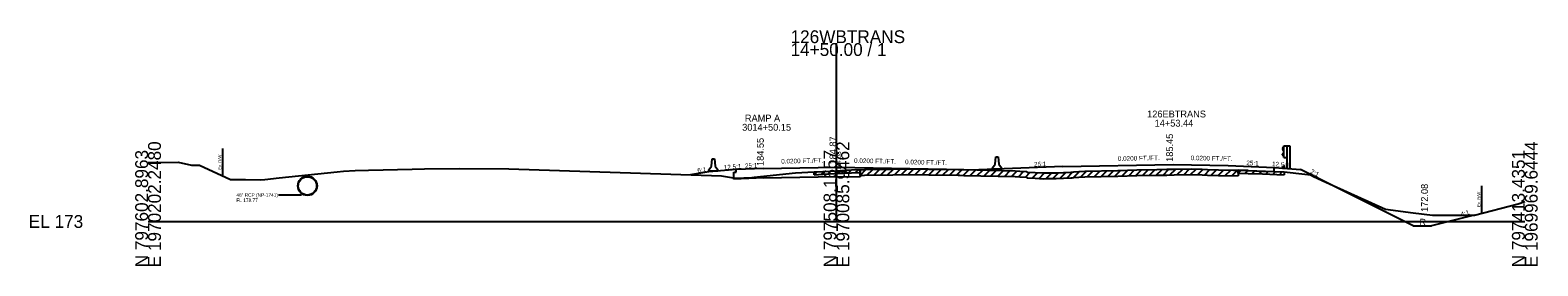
# Model space of a CAD drawing. Extents: x -6494 to 1970605, y -10 to 798140.
# Drawn here: x -25.7 to 302.8, y 6990.3 to 7041.8 of the extents above; entities that cross this region are included whole.
import ezdxf

# ---------------------------------------------------------------- set-up
doc = ezdxf.new("R2010")
doc.units = 0
for name, color, linetype in [('Default', 7, 'Continuous'), ('RD_GPK_XS_Cell', 7, 'Continuous'), ('RD_XS_Base', 7, 'Continuous'), ('RD_XS_CurbTop', 7, 'Continuous'), ('RD_XS_EarthShd', 7, 'Continuous'), ('RD_XS_ExGround', 7, 'Continuous'), ('RD_XS_ExPaveRet', 7, 'Continuous'), ('RD_XS_ExRW', 7, 'Continuous'), ('RD_XS_GR', 7, 'Continuous'), ('RD_XS_Misc_Line', 7, 'Continuous'), ('RD_XS_Pave', 7, 'Continuous'), ('RD_XS_PaveOvlay', 7, 'Continuous'), ('RD_XS_PaveShd', 7, 'Continuous'), ('RD_XS_Pipe', 7, 'Continuous'), ('RD_XS_TieSlope', 7, 'Continuous'), ('RD_XS_TX_Elev_EX', 7, 'Continuous'), ('RD_XS_TX_Elev_PR', 7, 'Continuous'), ('RD_XS_TX_Misc', 7, 'Continuous'), ('RD_XS_TX_MkPT', 7, 'Continuous'), ('RD_XS_TX_Profile', 7, 'Continuous'), ('RD_XS_TX_ShdSlope', 7, 'Continuous'), ('RD_XS_TX_Slope', 7, 'Continuous'), ('RD_XS_TX_Station', 7, 'Continuous')]:
    doc.layers.add(name, color=color, linetype=linetype)

msp = doc.modelspace()

# ---------------------------------------------------------------- linework, layer by layer
at = {"layer": 'Default'}
for p, q in [((122.16, 7011.24), (122.74, 7012.07)), ((122.16, 7010.99), (122.16, 7011.24)), ((124.16, 7010.99), (122.16, 7010.99)), ((122.74, 7012.07), (122.91, 7013.66)), ((122.91, 7013.66), (123.41, 7013.66)), ((123.41, 7013.66), (123.58, 7012.07)), ((123.58, 7012.07), (124.16, 7011.24)), ((124.16, 7011.24), (124.16, 7010.99)), ((184, 7011.67), (184.58, 7012.5)), ((184, 7011.42), (184, 7011.67)), ((186, 7011.42), (184, 7011.42)), ((184.58, 7012.5), (184.75, 7014.08)), ((184.75, 7014.08), (185.25, 7014.08)), ((185.25, 7014.08), (185.42, 7012.5)), ((185.42, 7012.5), (186, 7011.67)), ((186, 7011.67), (186, 7011.42))]:
    msp.add_line(p, q, dxfattribs=at)
at = {"layer": 'RD_GPK_XS_Cell'}
for p, q in [((150, 7000), (150, 7038.91)), ((0, 7000), (150, 7000)), ((150, 7000), (300, 7000))]:
    msp.add_line(p, q, dxfattribs=at)
at = {"layer": 'RD_XS_Base'}
for p, q in [((128.16, 7010.75), (128.16, 7011.31)), ((245.35, 7010.89), (245.35, 7011.81)), ((127.66, 7010.73), (128.16, 7010.75)), ((127.66, 7009.25), (127.66, 7010.73)), ((134.17, 7009.51), (127.66, 7009.25)), ((134.17, 7009.51), (138, 7009.59)), ((138, 7009.59), (150, 7009.83)), ((150, 7009.83), (155.15, 7009.73))]:
    msp.add_line(p, q, dxfattribs=at)
at = {"layer": 'RD_XS_CurbTop'}
for p, q in [((247.23, 7011.66), (247.47, 7012.12)), ((247.23, 7011.66), (247.69, 7011.62)), ((247.69, 7011.62), (247.63, 7012.06))]:
    msp.add_line(p, q, dxfattribs=at)
msp.add_ellipse((247.54, 7012.04), major_axis=(0, -0.131), ratio=0.686, start_param=1.762783, end_param=4.036677, dxfattribs=at)
at = {"layer": 'RD_XS_EarthShd'}
for p, q in [((128.16, 7011.31), (122.16, 7010.83)), ((245.35, 7011.81), (247.35, 7011.65))]:
    msp.add_line(p, q, dxfattribs=at)
at = {"layer": 'RD_XS_ExGround'}
msp.add_lwpolyline([(0, 7012.9), (6.53, 7012.97), (9.43, 7012.28), (11.23, 7012.29), (17.94, 7009.16), (20.84, 7009.14), (21.23, 7009.14), (24.41, 7009.12), (25.44, 7009.17), (28.59, 7009.49), (41.22, 7010.81), (42.59, 7010.95), (45.11, 7011.15), (48.04, 7011.21), (57.57, 7011.43), (60.26, 7011.47), (67.86, 7011.57), (78.64, 7011.45), (124.99, 7009.94), (128.04, 7009.42), (131.56, 7009.61), (132.09, 7009.66), (141.09, 7010.58), (145.14, 7010.81), (147.07, 7010.92), (150, 7011.08), (153.28, 7011.27), (156.11, 7011.32), (162.29, 7011.44), (165.17, 7011.5), (170.13, 7011.43), (176.5, 7011.34), (176.87, 7011.33), (177.74, 7011.31), (188.97, 7011.07), (189.98, 7011), (191.31, 7010.91), (191.56, 7010.79), (193.34, 7010.69), (195.2, 7010.58), (196.12, 7010.61), (197.9, 7010.63), (201.05, 7010.74), (201.38, 7010.76), (201.71, 7010.86), (202.79, 7010.91), (204.11, 7010.97), (211.34, 7011.15), (215.43, 7011.25), (219.78, 7011.34), (221.97, 7011.38), (223.62, 7011.41), (227.37, 7011.47), (229.69, 7011.4), (230.82, 7011.36), (233.25, 7011.3), (239.73, 7011.12), (242.84, 7010.99), (247.56, 7010.8), (252.08, 7010.31), (253.31, 7010.18), (253.84, 7009.89), (255.81, 7008.94), (258.22, 7007.87), (269.61, 7002.67), (275.64, 7001.89), (279.85, 7001.41), (281.07, 7001.41), (289.01, 7001.41), (298.56, 7003.87), (300, 7004.35)], dxfattribs=at)
at = {"layer": 'RD_XS_ExPaveRet'}
for p, q in [((155.15, 7010.05), (155.15, 7011.3)), ((155.15, 7011.3), (155.15, 7010.68)), ((237.56, 7011.18), (237.56, 7009.93)), ((237.56, 7010.55), (237.56, 7011.18)), ((145.14, 7010.18), (145.14, 7010.81)), ((145.14, 7010.18), (147.07, 7010.29)), ((147.07, 7010.29), (150, 7010.46)), ((150, 7010.46), (153.28, 7010.64)), ((153.28, 7010.64), (155.15, 7010.68)), ((155.15, 7010.05), (156.11, 7010.07)), ((156.11, 7010.07), (162.29, 7010.19)), ((162.29, 7010.19), (165.17, 7010.25)), ((165.17, 7010.25), (170.13, 7010.18)), ((170.13, 7010.18), (176.5, 7010.09)), ((176.5, 7010.09), (176.87, 7010.08)), ((176.87, 7010.08), (177.74, 7010.06)), ((177.74, 7010.06), (188.97, 7009.82)), ((188.97, 7009.82), (189.98, 7009.75)), ((189.98, 7009.75), (191.31, 7009.66)), ((191.31, 7009.66), (191.56, 7009.54)), ((191.56, 7009.54), (193.34, 7009.44)), ((193.34, 7009.44), (195.2, 7009.33)), ((195.2, 7009.33), (196.12, 7009.36)), ((196.12, 7009.36), (197.9, 7009.38)), ((197.9, 7009.38), (201.05, 7009.49)), ((201.05, 7009.49), (201.38, 7009.51)), ((201.38, 7009.51), (201.71, 7009.61)), ((201.71, 7009.61), (202.79, 7009.66)), ((202.79, 7009.66), (204.11, 7009.72)), ((204.11, 7009.72), (211.34, 7009.9)), ((211.34, 7009.9), (215.43, 7010)), ((215.43, 7010), (219.78, 7010.09)), ((219.78, 7010.09), (221.97, 7010.13)), ((221.97, 7010.13), (223.62, 7010.16)), ((223.62, 7010.16), (227.37, 7010.22)), ((227.37, 7010.22), (229.69, 7010.15)), ((229.69, 7010.15), (230.82, 7010.11)), ((230.82, 7010.11), (233.25, 7010.05)), ((233.25, 7010.05), (237.56, 7009.93)), ((237.56, 7010.55), (239.73, 7010.49)), ((239.73, 7010.49), (242.84, 7010.36)), ((242.84, 7010.36), (247.56, 7010.17)), ((247.56, 7010.8), (247.56, 7010.17))]:
    msp.add_line(p, q, dxfattribs=at)
at = {"layer": 'RD_XS_ExRW'}
for p, q in [((16.23, 7015.9), (16.23, 7009.9)), ((290.56, 7007.81), (290.56, 7001.81))]:
    msp.add_line(p, q, dxfattribs=at)
at = {"layer": 'RD_XS_GR'}
for p, q in [((247.5, 7016.36), (247.23, 7015.92)), ((247.23, 7015.92), (247.23, 7015.81)), ((247.23, 7015.81), (247.5, 7015.37)), ((247.23, 7014.67), (247.5, 7015.11)), ((247.23, 7014.56), (247.23, 7014.67)), ((247.5, 7014.12), (247.23, 7014.56)), ((247.5, 7016.53), (248.16, 7016.53)), ((247.5, 7013.96), (247.5, 7016.53)), ((248.16, 7016.53), (248.83, 7016.53)), ((248.16, 7016.53), (248.16, 7011.58)), ((248.83, 7016.53), (248.83, 7011.47)), ((247.5, 7013.96), (248.16, 7013.96))]:
    msp.add_line(p, q, dxfattribs=at)
at = {"layer": 'RD_XS_Misc_Line'}
for p, q in [((146.64, 7010.27), (147.31, 7010.93)), ((148.15, 7010.35), (148.81, 7011.01)), ((149.65, 7010.44), (150.31, 7011.1)), ((151.15, 7010.52), (151.81, 7011.18)), ((152.65, 7010.61), (153.31, 7011.27)), ((154.15, 7010.66), (154.79, 7011.29)), ((155.15, 7010.05), (156.42, 7011.32)), ((156.65, 7010.08), (157.92, 7011.35)), ((158.15, 7010.11), (159.43, 7011.38)), ((159.65, 7010.14), (160.93, 7011.41)), ((161.15, 7010.16), (162.43, 7011.44)), ((162.65, 7010.19), (163.93, 7011.47)), ((164.15, 7010.23), (165.42, 7011.5)), ((165.65, 7010.24), (166.89, 7011.48)), ((167.15, 7010.22), (168.39, 7011.46)), ((168.66, 7010.2), (169.89, 7011.44)), ((170.16, 7010.18), (171.39, 7011.42)), ((171.66, 7010.16), (172.89, 7011.39)), ((173.16, 7010.14), (174.39, 7011.37)), ((174.66, 7010.12), (175.89, 7011.35)), ((176.16, 7010.09), (177.39, 7011.32)), ((177.66, 7010.07), (178.88, 7011.29)), ((179.16, 7010.03), (180.38, 7011.26)), ((180.66, 7010), (181.89, 7011.22)), ((182.16, 7009.97), (183.39, 7011.19)), ((183.66, 7009.93), (184.89, 7011.16)), ((185.16, 7009.9), (186.39, 7011.12)), ((186.66, 7009.87), (187.89, 7011.09)), ((188.17, 7009.83), (189.37, 7011.04)), ((189.67, 7009.77), (190.84, 7010.94)), ((201.67, 7009.6), (202.99, 7010.92)), ((203.17, 7009.68), (204.48, 7010.98)), ((204.67, 7009.73), (205.96, 7011.02)), ((206.17, 7009.77), (207.46, 7011.05)), ((207.68, 7009.81), (208.96, 7011.09)), ((209.18, 7009.85), (210.46, 7011.13)), ((210.68, 7009.89), (211.96, 7011.17)), ((212.18, 7009.92), (213.46, 7011.2)), ((213.68, 7009.96), (214.96, 7011.24)), ((215.18, 7009.99), (216.46, 7011.27)), ((216.68, 7010.02), (217.96, 7011.3)), ((218.18, 7010.05), (219.46, 7011.33)), ((219.68, 7010.08), (220.96, 7011.36)), ((221.18, 7010.11), (222.46, 7011.39)), ((222.68, 7010.14), (223.96, 7011.42)), ((224.18, 7010.17), (225.45, 7011.44)), ((225.68, 7010.19), (226.95, 7011.46)), ((227.18, 7010.22), (228.41, 7011.44)), ((228.69, 7010.18), (229.9, 7011.39)), ((230.19, 7010.13), (231.4, 7011.34)), ((231.69, 7010.09), (232.91, 7011.31)), ((233.19, 7010.05), (234.41, 7011.26)), ((234.69, 7010.01), (235.91, 7011.22)), ((236.19, 7009.97), (237.41, 7011.18)), ((237.56, 7010.55), (238.16, 7011.16)), ((239.06, 7010.51), (239.67, 7011.12)), ((240.56, 7010.46), (241.16, 7011.06)), ((242.06, 7010.4), (242.66, 7011)), ((243.56, 7010.34), (244.16, 7010.94)), ((145.14, 7010.18), (145.81, 7010.85)), ((191.17, 7009.67), (192.25, 7010.75)), ((192.67, 7009.48), (193.85, 7010.66)), ((194.17, 7009.39), (195.36, 7010.59)), ((195.67, 7009.35), (196.94, 7010.62)), ((197.17, 7009.37), (198.45, 7010.65)), ((198.67, 7009.41), (199.97, 7010.7)), ((200.17, 7009.46), (201.51, 7010.8)), ((245.06, 7010.27), (245.66, 7010.87)), ((246.56, 7010.21), (247.16, 7010.81))]:
    msp.add_line(p, q, dxfattribs=at)
at = {"layer": 'RD_XS_Pave'}
for p, q in [((134.17, 7011.55), (138, 7011.63)), ((138, 7011.63), (150, 7011.87)), ((150, 7011.87), (174, 7011.39)), ((199.35, 7011.97), (223.35, 7012.45)), ((223.35, 7012.45), (235.35, 7012.21))]:
    msp.add_line(p, q, dxfattribs=at)
at = {"layer": 'RD_XS_PaveOvlay'}
for p, q in [((155.15, 7011.3), (156.11, 7011.32)), ((155.15, 7011.3), (155.15, 7009.73)), ((156.11, 7011.32), (162.29, 7011.44)), ((162.29, 7011.44), (165.17, 7011.5)), ((165.17, 7011.5), (170.13, 7011.43)), ((170.13, 7011.43), (176.5, 7011.34)), ((176.5, 7011.34), (176.87, 7011.33)), ((176.87, 7011.33), (177.74, 7011.31)), ((177.74, 7011.31), (188.92, 7011.07)), ((188.97, 7011.07), (189.98, 7011)), ((189.98, 7011), (191.31, 7010.91)), ((191.31, 7010.91), (191.56, 7010.79)), ((201.71, 7010.86), (202.79, 7010.91)), ((202.79, 7010.91), (204.11, 7010.97)), ((204.11, 7010.97), (211.34, 7011.15)), ((211.34, 7011.15), (215.43, 7011.25)), ((215.43, 7011.25), (219.78, 7011.34)), ((219.78, 7011.34), (221.97, 7011.38)), ((221.97, 7011.38), (223.62, 7011.41)), ((223.62, 7011.41), (227.37, 7011.47)), ((227.37, 7011.47), (229.69, 7011.4)), ((229.69, 7011.4), (230.82, 7011.36)), ((230.82, 7011.36), (233.25, 7011.3)), ((233.25, 7011.3), (237.56, 7011.18)), ((239.73, 7011.12), (237.56, 7011.18)), ((239.73, 7011.12), (245.35, 7010.89)), ((191.56, 7010.79), (193.34, 7010.69)), ((193.34, 7010.69), (195.2, 7010.58)), ((195.2, 7010.58), (196.12, 7010.61)), ((196.12, 7010.61), (197.9, 7010.63)), ((197.9, 7010.63), (201.05, 7010.74)), ((201.05, 7010.74), (201.38, 7010.76)), ((201.38, 7010.76), (201.71, 7010.86))]:
    msp.add_line(p, q, dxfattribs=at)
at = {"layer": 'RD_XS_PaveShd'}
for p, q in [((134.17, 7011.55), (128.16, 7011.31)), ((174, 7011.39), (181.03, 7011.24)), ((199.35, 7011.97), (181.03, 7011.24)), ((235.35, 7012.21), (245.35, 7011.81))]:
    msp.add_line(p, q, dxfattribs=at)
at = {"layer": 'RD_XS_Pipe'}
msp.add_line((33.4, 7005.77), (28.4, 7005.77), dxfattribs=at)
for radius in [2.1, 2]:
    msp.add_circle((34.73, 7007.77), radius, dxfattribs=at)
at = {"layer": 'RD_XS_TieSlope'}
for p, q in [((247.35, 7011.65), (251.1, 7011.35)), ((275.65, 6999.08), (251.1, 7011.35)), ((122.16, 7010.83), (118.18, 7010.17)), ((288.97, 7001.41), (279.65, 6999.08)), ((275.65, 6999.08), (279.65, 6999.08))]:
    msp.add_line(p, q, dxfattribs=at)

# ---------------------------------------------------------------- texts
at = {"layer": 'RD_GPK_XS_Cell'}
for s, p in [('126WBTRANS', (140, 7038.91)), ('14+50.00 / 1', (140, 7036.11)), ('EL 173', (-26, 6998.6))]:
    msp.add_text(s, height=2.8, dxfattribs=at).set_placement(p)
for s, p in [('N 797602.8963', (0, 6990)), ('E 1970202.2480', (2.8, 6990)), ('N 797508.1657', (150, 6990)), ('E 1970085.9462', (152.8, 6990)), ('N 797413.4351', (300, 6990)), ('E 1969969.6444', (302.8, 6990))]:
    msp.add_text(s, height=2.8, rotation=90, dxfattribs=at).set_placement(p)
at = {"layer": 'RD_XS_ExRW'}
for p in [(15.98, 7011.28), (290.31, 7003.19)]:
    msp.add_text('Ex. R/W ', height=0.65, rotation=90, dxfattribs=at).set_placement(p)
at = {"layer": 'RD_XS_Pipe'}
for s, p in [('48" RCP (NP-1741)', (19.25, 7005.4)), ('FL 178.77', (19.25, 7004.27))]:
    msp.add_text(s, height=0.75, dxfattribs=at).set_placement(p)
at = {"layer": 'RD_XS_TX_Elev_EX'}
msp.add_text('184.08', height=1, rotation=90, dxfattribs=at).set_placement((151, 7011.08))
at = {"layer": 'RD_XS_TX_Elev_PR'}
for s, p in [(' 184.55', (134.17, 7011.55)), (' 184.87', (150, 7011.87)), (' 185.45', (223.35, 7012.45))]:
    msp.add_text(s, height=1.5, rotation=90, dxfattribs=at).set_placement(p)
at = {"layer": 'RD_XS_TX_Misc'}
msp.add_text('172.08', height=1.5, rotation=90, dxfattribs=at).set_placement((278.9, 7002.08))
at = {"layer": 'RD_XS_TX_MkPT'}
msp.add_text('R', height=1.5, dxfattribs=at).set_placement((277.06, 6999.08))
at = {"layer": 'RD_XS_TX_Profile'}
for rotation, p in [(2.2906, (193.07, 7011.97)), (357.7094, (239.3, 7012.3))]:
    msp.add_text('25:1', height=1, rotation=rotation, dxfattribs=at).set_placement(p)
at = {"layer": 'RD_XS_TX_ShdSlope'}
for rotation, p in [(4.5739, (125.5, 7011.28)), (355.4262, (244.89, 7012.1))]:
    msp.add_text('12.5:1', height=1, rotation=rotation, dxfattribs=at).set_placement(p)
at = {"layer": 'RD_XS_TX_Slope'}
for s, rotation, p in [('0.0200 FT./FT.', 1.1442, (211.33, 7013.21)), ('0.0200 FT./FT.', 358.8527, (227.17, 7013.38)), ('6:1', 9.4564, (119.79, 7010.62)), ('25:1', 2.2891, (130.1, 7011.64)), ('0.0200 FT./FT.', 1.1458, (137.98, 7012.63)), ('0.0200 FT./FT.', 358.8542, (153.83, 7012.79)), ('0.0200 FT./FT.', 358.8542, (164.95, 7012.5)), ('2:1', 333.4349, (253.16, 7010.59)), ('4:1', 17.6196, (286.19, 7001.03))]:
    msp.add_text(s, height=1, rotation=rotation, dxfattribs=at).set_placement(p)
at = {"layer": 'RD_XS_TX_Station'}
for s, p in [('126EBTRANS', (217.7, 7022.7)), ('3014+50.15', (129.46, 7019.8)), ('RAMP A', (130.05, 7021.8)), ('14+53.44', (219.33, 7020.7))]:
    msp.add_text(s, height=1.5, dxfattribs=at).set_placement(p)

doc.saveas('drawing.dxf')
